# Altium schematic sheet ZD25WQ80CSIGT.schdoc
size 127 x 101 mm
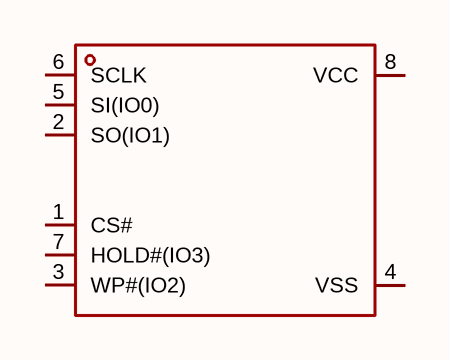
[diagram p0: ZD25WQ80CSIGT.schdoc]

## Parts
U?  zd25wq80csigt  [SOIC-8_L5.3-W5.3-P1.27-LS8.0-BL]  (value not drawn)

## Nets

Not connected (* = marked no-connect by the designer): U? 1(CS#) 2(SO(IO1)) 3(WP#(IO2)) 4(VSS) 5(SI(IO0)) 6(SCLK) 7(HOLD#(IO3)) 8(VCC)

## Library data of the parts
U? = zd25wq80csigt: 接口类型:SPI;存储容量:8Mbit;时钟频率(fc):104MHz;; Manufacturer: Zetta(澜智); AddInBom: yes; ModelId: f83d990ad74f400caf5ac920b7771508; ModelName: SOIC-8_L5.3-W5.3-H1.9-LS7.9-P1.27; ModelTransform: 208.661,311.25654,0,0,0,0,-0.0005,0.0005,0; Interface: SPI; Memory Size: 8Mbit; Clock Frequency: 104MHz; Voltage - Supply: 1.65V~3.6V; Standby Supply Current: 1.3uA; Program / Erase Cycles: 100000次; Page Programming Time (Tpp): 1.5ms; Block Erase Time(tBE): 15ms; Data Retention - TDR (Year): 20年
